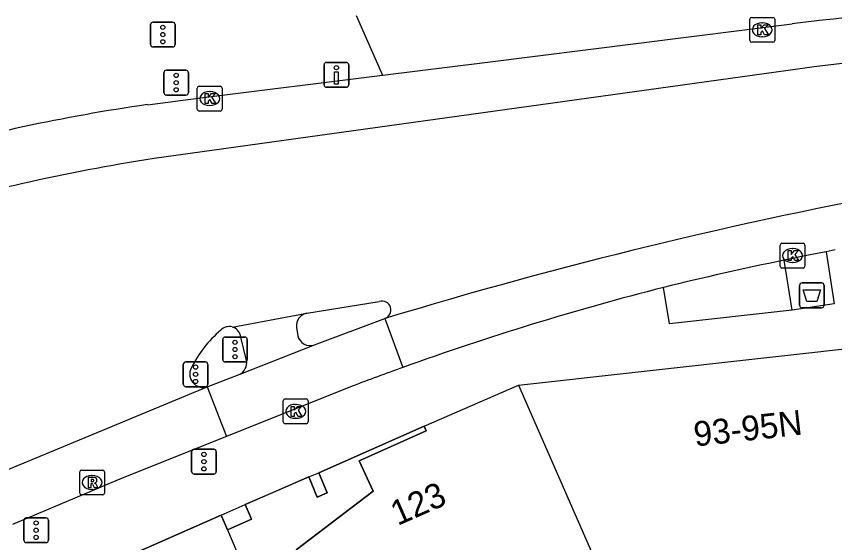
# Model space of a CAD drawing. Extents: x 160664 to 161506, y 382245 to 383288.
# Drawn here: x 161006.23 to 161039.18, y 382914.09 to 382935.28 of the extents above; entities that cross this region are included whole.
import ezdxf

# ---------------------------------------------------------------- set-up
doc = ezdxf.new("R2010")
doc.units = 0
for name, color, linetype in [('IMGEO_Afval_apart_plaats', 7, 'Continuous'), ('IMGEO_Drukknoppaal', 7, 'Continuous'), ('IMGEO_Fietspad_gesloten', 7, 'Continuous'), ('IMGEO_Kolk', 7, 'Continuous'), ('IMGEO_Pand', 7, 'Continuous'), ('IMGEO_Pand_nummerreeks', 7, 'Continuous'), ('IMGEO_Pand_overbouw', 7, 'Continuous'), ('IMGEO_Rijbaan_lokaal_gesloten', 7, 'Continuous'), ('IMGEO_Rijbaan_lokaal_open', 7, 'Continuous'), ('IMGEO_Rioolput', 7, 'Continuous'), ('IMGEO_Verkeersregelinstallatiepaal', 7, 'Continuous'), ('IMGEO_Voetpad_gesloten', 7, 'Continuous'), ('IMGEO_Voetpad_open', 7, 'Continuous')]:
    doc.layers.add(name, color=color, linetype=linetype)

msp = doc.modelspace()

# ---------------------------------------------------------------- linework, layer by layer
at = {"layer": 'IMGEO_Afval_apart_plaats'}
for p, q in [((161037.77, 382923.649), (161037.77, 382924.449)), ((161037.77, 382924.449), (161037.77, 382923.649)), ((161037.87, 382924.549), (161038.66, 382924.549)), ((161038.66, 382924.549), (161037.87, 382924.549)), ((161038.76, 382924.449), (161038.76, 382923.649)), ((161038.76, 382923.649), (161038.76, 382924.449)), ((161038.66, 382923.549), (161037.87, 382923.549)), ((161037.87, 382923.549), (161038.66, 382923.549))]:
    msp.add_line(p, q, dxfattribs=at)
msp.add_lwpolyline([(161037.913, 382924.263), (161038.617, 382924.263), (161038.468, 382923.793), (161038.062, 382923.793), (161037.913, 382924.263)], dxfattribs=at)
for centre, start, end in [((161037.87, 382924.449), 90, 180), ((161037.87, 382924.449), 90, 180), ((161038.66, 382924.449), 0, 90), ((161038.66, 382924.449), 360, 90), ((161037.87, 382923.649), 180, 270), ((161037.87, 382923.649), 180, 270), ((161038.66, 382923.649), 270, 0), ((161038.66, 382923.649), 270, 0)]:
    msp.add_arc(centre, 0.1, start, end, dxfattribs=at)
at = {"layer": 'IMGEO_Drukknoppaal'}
for p, q in [((161018.725, 382933.428), (161019.515, 382933.428)), ((161019.515, 382933.428), (161018.725, 382933.428)), ((161018.625, 382932.528), (161018.625, 382933.328)), ((161018.625, 382933.328), (161018.625, 382932.528)), ((161019.615, 382933.328), (161019.615, 382932.528)), ((161019.615, 382932.528), (161019.615, 382933.328)), ((161019.515, 382932.428), (161018.725, 382932.428)), ((161018.725, 382932.428), (161019.515, 382932.428))]:
    msp.add_line(p, q, dxfattribs=at)
msp.add_lwpolyline([(161019.195, 382933.053), (161019.195, 382932.553), (161019.045, 382932.553), (161019.045, 382933.053), (161019.195, 382933.053)], dxfattribs=at)
msp.add_circle((161019.12, 382933.218), 0.085, dxfattribs=at)
for centre, start, end in [((161018.725, 382933.328), 90, 180), ((161018.725, 382933.328), 90, 180), ((161019.515, 382933.328), 0, 90), ((161019.515, 382933.328), 360, 90), ((161018.725, 382932.528), 180, 270), ((161018.725, 382932.528), 180, 270), ((161019.515, 382932.528), 270, 0), ((161019.515, 382932.528), 270, 0)]:
    msp.add_arc(centre, 0.1, start, end, dxfattribs=at)
at = {"layer": 'IMGEO_Fietspad_gesloten'}
for points in [[(161018.238, 382922.048), (161021.068, 382923.113)], [(161015.208, 382920.862), (161018.238, 382922.048)], [(161013.921, 382920.363), (161015.208, 382920.862)], [(161019.75, 382920.387), (161014.701, 382918.365)]]:
    msp.add_lwpolyline(points, dxfattribs=at)
msp.add_arc((161059.209, 382816.921), 110.735, 109.74541, 110.87535, dxfattribs=at)
at = {"layer": 'IMGEO_Kolk'}
for p, q in [((161035.77, 382934.317), (161035.77, 382935.169)), ((161035.845, 382935.243), (161036.697, 382935.243)), ((161036.258, 382935.023), (161036.283, 382935.023)), ((161036.771, 382935.169), (161036.771, 382934.317)), ((161036.281, 382934.463), (161036.256, 382934.463)), ((161036.697, 382934.243), (161035.845, 382934.243)), ((161013.518, 382931.546), (161013.518, 382932.398)), ((161013.593, 382932.472), (161014.445, 382932.472)), ((161014.519, 382932.398), (161014.519, 382931.546)), ((161014.006, 382932.252), (161014.031, 382932.252)), ((161014.029, 382931.692), (161014.004, 382931.692)), ((161014.445, 382931.472), (161013.593, 382931.472)), ((161037.064, 382926.148), (161037.916, 382926.148)), ((161036.989, 382925.222), (161036.989, 382926.074)), ((161037.477, 382925.928), (161037.502, 382925.928)), ((161037.99, 382926.074), (161037.99, 382925.222)), ((161037.916, 382925.148), (161037.064, 382925.148)), ((161037.5, 382925.368), (161037.475, 382925.368)), ((161017.057, 382919.874), (161017.909, 382919.874)), ((161016.982, 382918.948), (161016.982, 382919.8)), ((161017.47, 382919.654), (161017.495, 382919.654)), ((161017.983, 382919.8), (161017.983, 382918.948)), ((161017.909, 382918.874), (161017.057, 382918.874)), ((161017.493, 382919.094), (161017.468, 382919.094))]:
    msp.add_line(p, q, dxfattribs=at)
for points in [[(161035.77, 382934.317), (161035.77, 382935.169)], [(161035.845, 382935.243), (161036.697, 382935.243)], [(161036.771, 382935.169), (161036.771, 382934.317)], [(161036.091, 382934.943), (161036.214, 382934.943), (161036.214, 382934.792), (161036.344, 382934.943), (161036.508, 382934.943), (161036.362, 382934.792), (161036.515, 382934.543), (161036.363, 382934.543), (161036.278, 382934.707), (161036.214, 382934.64), (161036.214, 382934.543), (161036.091, 382934.543), (161036.091, 382934.943)], [(161036.697, 382934.243), (161035.845, 382934.243)], [(161013.518, 382931.546), (161013.518, 382932.398)], [(161013.593, 382932.472), (161014.445, 382932.472)], [(161014.519, 382932.398), (161014.519, 382931.546)], [(161013.839, 382932.172), (161013.962, 382932.172), (161013.962, 382932.021), (161014.092, 382932.172), (161014.256, 382932.172), (161014.11, 382932.021), (161014.263, 382931.772), (161014.111, 382931.772), (161014.026, 382931.936), (161013.962, 382931.869), (161013.962, 382931.772), (161013.839, 382931.772), (161013.839, 382932.172)], [(161014.445, 382931.472), (161013.593, 382931.472)], [(161037.064, 382926.148), (161037.916, 382926.148)], [(161036.989, 382925.222), (161036.989, 382926.074)], [(161037.31, 382925.848), (161037.433, 382925.848), (161037.433, 382925.697), (161037.563, 382925.848), (161037.727, 382925.848), (161037.581, 382925.697), (161037.734, 382925.448), (161037.582, 382925.448), (161037.497, 382925.612), (161037.433, 382925.545), (161037.433, 382925.448), (161037.31, 382925.448), (161037.31, 382925.848)], [(161037.99, 382926.074), (161037.99, 382925.222)], [(161037.916, 382925.148), (161037.064, 382925.148)], [(161017.057, 382919.874), (161017.909, 382919.874)], [(161016.982, 382918.948), (161016.982, 382919.8)], [(161017.303, 382919.574), (161017.426, 382919.574), (161017.426, 382919.423), (161017.556, 382919.574), (161017.72, 382919.574), (161017.574, 382919.423), (161017.727, 382919.174), (161017.575, 382919.174), (161017.49, 382919.338), (161017.426, 382919.271), (161017.426, 382919.174), (161017.303, 382919.174), (161017.303, 382919.574)], [(161017.983, 382919.8), (161017.983, 382918.948)], [(161017.909, 382918.874), (161017.057, 382918.874)]]:
    msp.add_lwpolyline(points, dxfattribs=at)
for centre, start, end in [((161035.847, 382935.167), 91.552, 178.448), ((161035.847, 382935.167), 91.552, 178.448), ((161036.695, 382935.167), 1.552, 88.448), ((161036.695, 382935.167), 1.552, 88.448), ((161035.847, 382934.319), 181.552, 268.448), ((161035.847, 382934.319), 181.552, 268.448), ((161036.695, 382934.319), 271.552, 358.448), ((161036.695, 382934.319), 271.552, 358.448), ((161013.595, 382932.396), 91.552, 178.448), ((161013.595, 382932.396), 91.552, 178.448), ((161014.443, 382932.396), 1.552, 88.448), ((161014.443, 382932.396), 1.552, 88.448), ((161013.595, 382931.548), 181.552, 268.448), ((161013.595, 382931.548), 181.552, 268.448), ((161014.443, 382931.548), 271.552, 358.448), ((161014.443, 382931.548), 271.552, 358.448), ((161037.066, 382926.072), 91.552, 178.448), ((161037.066, 382926.072), 91.552, 178.448), ((161037.914, 382926.072), 1.552, 88.448), ((161037.914, 382926.072), 1.552, 88.448), ((161037.066, 382925.224), 181.552, 268.448), ((161037.066, 382925.224), 181.552, 268.448), ((161037.914, 382925.224), 271.552, 358.448), ((161037.914, 382925.224), 271.552, 358.448), ((161017.059, 382919.798), 91.552, 178.448), ((161017.059, 382919.798), 91.552, 178.448), ((161017.907, 382919.798), 1.552, 88.448), ((161017.907, 382919.798), 1.552, 88.448), ((161017.059, 382918.95), 181.552, 268.448), ((161017.059, 382918.95), 181.552, 268.448), ((161017.907, 382918.95), 271.552, 358.448), ((161017.907, 382918.95), 271.552, 358.448)]:
    msp.add_arc(centre, 0.0765, start, end, dxfattribs=at)
for centre, major_axis, ratio, start_param, end_param in [((161036.257, 382934.743), (-0.387, 0.002), 0.722429, 4.712389, 7.853982), ((161036.282, 382934.743), (-0.39, 0.002), 0.717154, 1.570796, 4.712389), ((161014.005, 382931.972), (-0.387, 0.002), 0.722429, 4.712389, 7.853982), ((161014.03, 382931.972), (-0.39, 0.002), 0.717154, 1.570796, 4.712389), ((161037.476, 382925.648), (-0.387, 0.002), 0.722429, 4.712389, 7.853982), ((161037.501, 382925.648), (-0.39, 0.002), 0.717154, 1.570796, 4.712389), ((161017.469, 382919.374), (-0.387, 0.002), 0.722429, 4.712389, 7.853982), ((161017.494, 382919.374), (-0.39, 0.002), 0.717154, 1.570796, 4.712389)]:
    msp.add_ellipse(centre, major_axis=major_axis, ratio=ratio, start_param=start_param, end_param=end_param, dxfattribs=at)
at = {"layer": 'IMGEO_Pand'}
for points in [[(161026.456, 382920.431), (161046.091, 382922.612), (161046.345, 382922.64)], [(161022.658, 382918.777), (161026.456, 382920.431)], [(161026.456, 382920.431), (161033.8, 382903.661)], [(161022.658, 382918.777), (161022.735, 382918.593), (161020.035, 382917.387), (161020.603, 382916.161), (161017.496, 382913.799), (161018.294, 382911.972), (161018.193, 382911.923), (161022.524, 382902.347), (161023.07, 382901.081)], [(161018.01, 382916.731), (161018.411, 382916.899)], [(161018.01, 382916.731), (161018.348, 382915.923), (161018.749, 382916.091), (161018.411, 382916.899)], [(161014.477, 382915.191), (161015.441, 382915.623)], [(161014.74, 382914.604), (161015.704, 382915.036), (161015.441, 382915.623)], [(161014.477, 382915.191), (161014.74, 382914.604)]]:
    msp.add_lwpolyline(points, dxfattribs=at)
at = {"layer": 'IMGEO_Pand_overbouw'}
msp.add_lwpolyline([(161017.496, 382913.799), (161020.603, 382916.161), (161020.035, 382917.387), (161022.735, 382918.593), (161022.658, 382918.777), (161018.411, 382916.899), (161018.749, 382916.091), (161018.348, 382915.923), (161018.01, 382916.731), (161016.478, 382916.07), (161015.441, 382915.623), (161015.704, 382915.036), (161014.74, 382914.604), (161014.477, 382915.191), (161008.532, 382912.58)], dxfattribs=at)
at = {"layer": 'IMGEO_Rijbaan_lokaal_gesloten'}
for points in [[(161020.977, 382932.92), (161025.093, 382933.433), (161037.47, 382934.988)], [(161037.79, 382933.174), (161011.778, 382929.564)], [(161011.513, 382931.727), (161013.66, 382932.007), (161020.977, 382932.92)], [(161039.209, 382925.877), (161038.841, 382925.806)], [(161017.93, 382923.325), (161020.847, 382923.804)], [(161014.927, 382922.772), (161017.93, 382923.325)], [(161021.068, 382923.113), (161021.798, 382921.145)], [(161005.277, 382916.775), (161013.921, 382920.363)], [(161013.921, 382920.363), (161014.701, 382918.365)], [(161014.701, 382918.365), (161010.491, 382916.679), (161006.081, 382914.822)]]:
    msp.add_lwpolyline(points, dxfattribs=at)
for centre, radius, start, end in [((161077.257, 382597.76), 339.566, 93.73679, 96.72873), ((161065.688, 382722.808), 212.208, 92.63145, 97.55421), ((161021.311, 382862.511), 69.907, 98.05719, 106.40828), ((161024.937, 382846.684), 83.918, 99.02197, 106.37076), ((161077.931, 382735.933), 195.626, 100.4143, 106.89826), ((161065.807, 382787.466), 140.943, 101.03023, 101.73269), ((161066.518, 382784.376), 144.113, 101.75949, 103.73778), ((161060.907, 382812.45), 115.517, 104.34124, 109.78901), ((161020.95, 382923.456), 0.363, 289.0006, 106.4707), ((161017.486, 382919.053), 4.691, 130.0953, 153.8897), ((161014.803, 382922.329), 0.461, 74.3189, 137.1127), ((161013.755, 382920.876), 0.539, 153.2555, 287.9346)]:
    msp.add_arc(centre, radius, start, end, dxfattribs=at)
at = {"layer": 'IMGEO_Rijbaan_lokaal_open'}
for points in [[(161008.532, 382912.58), (161014.477, 382915.191)], [(161014.74, 382914.604), (161016.195, 382911.155)]]:
    msp.add_lwpolyline(points, dxfattribs=at)
at = {"layer": 'IMGEO_Rioolput'}
for p, q in [((161008.782, 382916.084), (161008.782, 382916.936)), ((161008.857, 382917.01), (161009.709, 382917.01)), ((161009.783, 382916.936), (161009.783, 382916.084)), ((161009.27, 382916.79), (161009.295, 382916.79)), ((161009.293, 382916.23), (161009.268, 382916.23)), ((161009.709, 382916.01), (161008.857, 382916.01))]:
    msp.add_line(p, q, dxfattribs=at)
for points in [[(161008.782, 382916.084), (161008.782, 382916.936)], [(161008.857, 382917.01), (161009.709, 382917.01)], [(161009.783, 382916.936), (161009.783, 382916.084)], [(161009.371, 382916.708), (161009.119, 382916.71), (161009.119, 382916.31)], [(161009.297, 382916.629), (161009.243, 382916.629), (161009.243, 382916.548)], [(161009.243, 382916.548), (161009.295, 382916.548)], [(161009.119, 382916.31), (161009.243, 382916.31), (161009.243, 382916.472), (161009.254, 382916.472)], [(161009.301, 382916.443), (161009.372, 382916.31), (161009.512, 382916.31), (161009.447, 382916.436)], [(161009.709, 382916.01), (161008.857, 382916.01)]]:
    msp.add_lwpolyline(points, dxfattribs=at)
for centre, radius, start, end in [((161008.859, 382916.934), 0.0765, 91.552, 178.448), ((161008.859, 382916.934), 0.0765, 91.552, 178.448), ((161009.707, 382916.934), 0.0765, 1.552, 88.448), ((161009.707, 382916.934), 0.0765, 1.552, 88.448), ((161009.279, 382916.737), 0.19, 274.7715, 282.9687), ((161009.303, 382916.533), 0.0964, 77.0061, 93.1865), ((161009.317, 382916.59), 0.0378, 276.6634, 79.6772), ((161009.37, 382916.598), 0.109, 350.3612, 89.416), ((161009.368, 382916.598), 0.112, 277.5842, 350.9817), ((161009.253, 382916.419), 0.0533, 26.0293, 88.6989), ((161009.352, 382916.383), 0.108, 29.5134, 73.7905), ((161008.859, 382916.086), 0.0765, 181.552, 268.448), ((161008.859, 382916.086), 0.0765, 181.552, 268.448), ((161009.707, 382916.086), 0.0765, 271.552, 358.448), ((161009.707, 382916.086), 0.0765, 271.552, 358.448)]:
    msp.add_arc(centre, radius, start, end, dxfattribs=at)
for centre, major_axis, ratio, start_param, end_param in [((161009.269, 382916.51), (-0.387, 0.002), 0.722429, 4.712389, 7.853982), ((161009.294, 382916.51), (-0.39, 0.002), 0.717154, 1.570796, 4.712389)]:
    msp.add_ellipse(centre, major_axis=major_axis, ratio=ratio, start_param=start_param, end_param=end_param, dxfattribs=at)
at = {"layer": 'IMGEO_Verkeersregelinstallatiepaal'}
for p, q in [((161011.736, 382935.051), (161012.526, 382935.051)), ((161012.526, 382935.051), (161011.736, 382935.051)), ((161011.636, 382934.151), (161011.636, 382934.951)), ((161011.636, 382934.951), (161011.636, 382934.151)), ((161012.626, 382934.951), (161012.626, 382934.151)), ((161012.626, 382934.151), (161012.626, 382934.951)), ((161012.526, 382934.051), (161011.736, 382934.051)), ((161011.736, 382934.051), (161012.526, 382934.051)), ((161012.173, 382932.216), (161012.173, 382933.016)), ((161012.173, 382933.016), (161012.173, 382932.216)), ((161012.273, 382933.116), (161013.063, 382933.116)), ((161013.063, 382933.116), (161012.273, 382933.116)), ((161013.163, 382933.016), (161013.163, 382932.216)), ((161013.163, 382932.216), (161013.163, 382933.016)), ((161013.063, 382932.116), (161012.273, 382932.116)), ((161012.273, 382932.116), (161013.063, 382932.116)), ((161014.542, 382921.466), (161014.542, 382922.266)), ((161014.542, 382922.266), (161014.542, 382921.466)), ((161014.642, 382922.366), (161015.432, 382922.366)), ((161015.432, 382922.366), (161014.642, 382922.366)), ((161015.532, 382922.266), (161015.532, 382921.466)), ((161015.532, 382921.466), (161015.532, 382922.266)), ((161012.954, 382920.468), (161012.954, 382921.268)), ((161012.954, 382921.268), (161012.954, 382920.468)), ((161013.054, 382921.368), (161013.844, 382921.368)), ((161013.844, 382921.368), (161013.054, 382921.368)), ((161013.944, 382921.268), (161013.944, 382920.468)), ((161013.944, 382920.468), (161013.944, 382921.268)), ((161015.432, 382921.366), (161014.642, 382921.366)), ((161014.642, 382921.366), (161015.432, 382921.366)), ((161013.844, 382920.368), (161013.054, 382920.368)), ((161013.054, 382920.368), (161013.844, 382920.368)), ((161013.39, 382917.849), (161014.18, 382917.849)), ((161014.18, 382917.849), (161013.39, 382917.849)), ((161013.29, 382916.949), (161013.29, 382917.749)), ((161013.29, 382917.749), (161013.29, 382916.949)), ((161014.28, 382917.749), (161014.28, 382916.949)), ((161014.28, 382916.949), (161014.28, 382917.749)), ((161014.18, 382916.849), (161013.39, 382916.849)), ((161013.39, 382916.849), (161014.18, 382916.849)), ((161006.533, 382914.186), (161006.533, 382914.986)), ((161006.533, 382914.986), (161006.533, 382914.186)), ((161006.633, 382915.086), (161007.423, 382915.086)), ((161007.423, 382915.086), (161006.633, 382915.086)), ((161007.523, 382914.986), (161007.523, 382914.186)), ((161007.523, 382914.186), (161007.523, 382914.986)), ((161007.423, 382914.086), (161006.633, 382914.086)), ((161006.633, 382914.086), (161007.423, 382914.086))]:
    msp.add_line(p, q, dxfattribs=at)
for centre in [(161012.131, 382934.841), (161012.131, 382934.551), (161012.131, 382934.261), (161012.668, 382932.906), (161012.668, 382932.616), (161012.668, 382932.326), (161015.037, 382922.156), (161015.037, 382921.866), (161015.037, 382921.576), (161013.449, 382921.158), (161013.449, 382920.868), (161013.449, 382920.578), (161013.785, 382917.639), (161013.785, 382917.349), (161013.785, 382917.059), (161007.028, 382914.876), (161007.028, 382914.586), (161007.028, 382914.296)]:
    msp.add_circle(centre, 0.085, dxfattribs=at)
for centre, start, end in [((161011.736, 382934.951), 90, 180), ((161011.736, 382934.951), 90, 180), ((161012.526, 382934.951), 0, 90), ((161012.526, 382934.951), 360, 90), ((161011.736, 382934.151), 180, 270), ((161011.736, 382934.151), 180, 270), ((161012.526, 382934.151), 270, 0), ((161012.526, 382934.151), 270, 0), ((161012.273, 382933.016), 90, 180), ((161012.273, 382933.016), 90, 180), ((161013.063, 382933.016), 0, 90), ((161013.063, 382933.016), 360, 90), ((161012.273, 382932.216), 180, 270), ((161012.273, 382932.216), 180, 270), ((161013.063, 382932.216), 270, 0), ((161013.063, 382932.216), 270, 0), ((161014.642, 382922.266), 90, 180), ((161014.642, 382922.266), 90, 180), ((161015.432, 382922.266), 0, 90), ((161015.432, 382922.266), 360, 90), ((161013.054, 382921.268), 90, 180), ((161013.054, 382921.268), 90, 180), ((161013.844, 382921.268), 0, 90), ((161013.844, 382921.268), 360, 90), ((161014.642, 382921.466), 180, 270), ((161014.642, 382921.466), 180, 270), ((161015.432, 382921.466), 270, 0), ((161015.432, 382921.466), 270, 0), ((161013.054, 382920.468), 180, 270), ((161013.054, 382920.468), 180, 270), ((161013.844, 382920.468), 270, 0), ((161013.844, 382920.468), 270, 0), ((161013.39, 382917.749), 90, 180), ((161013.39, 382917.749), 90, 180), ((161014.18, 382917.749), 0, 90), ((161014.18, 382917.749), 360, 90), ((161013.39, 382916.949), 180, 270), ((161013.39, 382916.949), 180, 270), ((161014.18, 382916.949), 270, 0), ((161014.18, 382916.949), 270, 0), ((161006.633, 382914.986), 90, 180), ((161006.633, 382914.986), 90, 180), ((161007.423, 382914.986), 0, 90), ((161007.423, 382914.986), 360, 90), ((161006.633, 382914.186), 180, 270), ((161006.633, 382914.186), 180, 270), ((161007.423, 382914.186), 270, 0), ((161007.423, 382914.186), 270, 0)]:
    msp.add_arc(centre, 0.1, start, end, dxfattribs=at)
at = {"layer": 'IMGEO_Voetpad_gesloten'}
for points in [[(161038.841, 382925.806), (161039.159, 382923.709), (161037.474, 382923.453)], [(161037.474, 382923.453), (161037.147, 382925.465)]]:
    msp.add_lwpolyline(points, dxfattribs=at)
at = {"layer": 'IMGEO_Voetpad_open'}
for points in [[(161019.914, 382935.326), (161020.977, 382932.92)], [(161037.474, 382923.453), (161032.535, 382922.904), (161032.294, 382924.367)], [(161017.508, 382922.756), (161017.562, 382922.42)], [(161015.504, 382921.427), (161015.256, 382922.418)], [(161018.411, 382916.899), (161022.658, 382918.777)], [(161015.441, 382915.623), (161018.01, 382916.731)]]:
    msp.add_lwpolyline(points, dxfattribs=at)
for centre, radius, start, end in [((161018.032, 382922.808), 0.527, 101.1817, 185.6932), ((161014.8, 382922.324), 0.466, 11.6565, 74.1509), ((161018.073, 382922.548), 0.526, 194.035, 288.3174), ((161014.987, 382921.338), 0.525, 294.9445, 9.756)]:
    msp.add_arc(centre, radius, start, end, dxfattribs=at)

# ---------------------------------------------------------------- texts
at = {"layer": 'IMGEO_Pand_nummerreeks'}
for s, rotation, p in [('93-95N', 6.4117, (161033.565, 382917.955)), ('123', 23.6893, (161021.584, 382914.756))]:
    msp.add_text(s, height=1, rotation=rotation, dxfattribs=at).set_placement(p)

doc.saveas('drawing.dxf')
